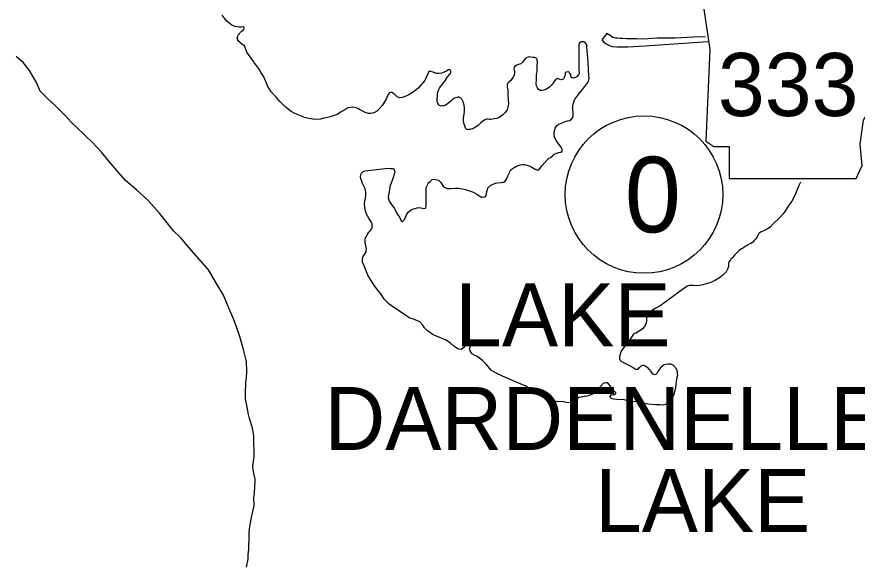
# Model space of a CAD drawing. Extents: x 31699 to 244310, y -8841 to 11474.
# Drawn here: x 95308.6 to 95778.2, y 4155.7 to 4462.2 of the extents above; entities that cross this region are included whole.
import ezdxf

# ---------------------------------------------------------------- set-up
doc = ezdxf.new("R2010")
doc.units = 0
for name, color, linetype in [('G-ANNO-TEXT', 7, 'Continuous'), ('R_Border Notes', 7, 'Continuous'), ('R_Draft', 7, 'Continuous'), ('R_Logo', 7, 'Continuous')]:
    doc.layers.add(name, color=color, linetype=linetype)

msp = doc.modelspace()

# ---------------------------------------------------------------- linework, layer by layer
at = {"layer": 'G-ANNO-TEXT'}
msp.add_lwpolyline([(95690.79, 4477.79), (95695.87, 4443.96), (95693.61, 4392.64), (95698.12, 4389.82), (95706.58, 4389.82), (95706.58, 4371.77), (95777.64, 4371.77), (95781.02, 4379.1), (95779.89, 4390.95), (95781.59, 4404.48), (95787.79, 4415.2), (95791.74, 4423.09), (95797.38, 4431.55), (95800.76, 4440.57), (95803.58, 4447.9), (95808.65, 4454.11), (95809.78, 4458.05), (95807.53, 4460.87), (95790.05, 4460.87), (95793.99, 4468.77), (95794.56, 4473.84), (95792.22, 4477.74)], close=True, dxfattribs=at)
at = {"layer": 'R_Border Notes'}
msp.add_circle((95659.04, 4362.88), 44, dxfattribs=at)
at = {"layer": 'R_Draft'}
for points in [[(95435.67, 4446.36), (95435.21, 4446.14), (95434.18, 4447.04), (95433.49, 4447.75), (95433.22, 4448.01), (95432.47, 4448.66), (95432.19, 4449.12), (95432.04, 4449.72), (95431.82, 4450.31), (95432, 4450.85), (95432.11, 4451.66), (95432.49, 4452.34), (95432.88, 4452.62), (95433.08, 4452.69), (95433.46, 4453.37), (95433.84, 4453.85), (95434.23, 4454.2), (95434.49, 4454.47), (95435.2, 4454.96), (95435.33, 4455.17), (95435.52, 4455.37), (95435.65, 4455.71), (95435.64, 4455.98), (95435.49, 4456.37), (95434.82, 4456.69), (95434.03, 4456.4), (95433.56, 4456.38), (95432.76, 4456.49), (95430.48, 4456.89), (95428.67, 4457.57), (95427.03, 4458.92), (95425.87, 4459.82), (95424.48, 4461.65), (95423.3, 4463.22)], [(95693.33, 4450.95), (95686.8, 4450.79), (95676.42, 4450.35), (95666.64, 4450.19), (95658.39, 4449.79), (95654.93, 4449.87), (95649.2, 4449.97), (95647.13, 4450.14), (95645.67, 4450.18), (95644.27, 4450.23), (95643.14, 4450.21), (95642.4, 4450.4), (95641.6, 4450.72), (95640.18, 4451.83), (95638.23, 4452.8), (95635.49, 4449.42)], [(95587.78, 4378.76), (95589.96, 4379.46), (95591.43, 4379.69), (95592.36, 4379.7), (95593.56, 4379.39), (95595.3, 4378.68), (95596.38, 4378.1), (95597.25, 4377.65), (95598.26, 4377.13), (95599.2, 4376.61), (95600.2, 4376.76), (95600.72, 4377.03), (95601.5, 4378.32), (95602.22, 4379.13), (95605.23, 4382.65), (95605.95, 4383.13), (95606.74, 4383.67), (95608.05, 4384.76), (95608.91, 4385.38), (95610.03, 4385.86), (95611.29, 4386.35), (95612.62, 4386.64), (95613.34, 4387.12), (95613.32, 4388.25), (95612.64, 4389.58), (95611.07, 4391.55), (95610.32, 4392.61), (95609.57, 4393.8), (95609.02, 4395.06), (95608.87, 4395.72), (95608.85, 4397.06), (95609.09, 4398.6), (95609.47, 4399.94), (95610.38, 4401.49), (95611.5, 4402.24), (95613.35, 4403), (95615.2, 4403.7), (95616.33, 4403.99), (95617.39, 4404.34), (95618.38, 4404.82), (95619.23, 4405.97), (95619.41, 4406.91), (95619.4, 4407.71), (95619.38, 4408.91), (95619.29, 4410.24), (95619.27, 4411.11), (95619.25, 4412.58), (95619.56, 4414.05), (95619.75, 4414.72), (95620.26, 4415.8), (95621.24, 4417.28), (95622.35, 4418.57), (95623.78, 4420.46), (95624.7, 4421.61), (95626.39, 4423.91), (95627.24, 4424.99), (95627.95, 4426.27), (95628.32, 4427.74), (95628.29, 4430.01), (95628.06, 4431.81), (95627.95, 4434.41), (95627.93, 4435.61), (95627.84, 4436.81), (95627.44, 4441.28), (95627.28, 4442.47), (95627.27, 4443.14), (95627.1, 4445.41), (95627.02, 4446.21), (95627.02, 4446.27), (95627.09, 4446.28), (95627.02, 4446.27), (95626.95, 4446.74), (95626.74, 4447.14), (95626.33, 4447.66), (95626.06, 4447.86), (95625.39, 4448.25), (95624.86, 4448.31), (95623.99, 4448.29), (95623.2, 4447.81), (95622.62, 4446.87), (95622.55, 4443.13), (95622.67, 4439.8), (95622.7, 4437.79), (95622.6, 4435.92), (95622.62, 4434.32), (95622.65, 4432.79), (95622.74, 4430.99), (95622.75, 4430.45), (95622.56, 4429.92), (95622.04, 4429.37), (95621.71, 4428.9), (95620.46, 4428.15), (95620.19, 4428.08), (95619.4, 4428), (95619.06, 4428.06), (95618.79, 4428.19), (95618.39, 4428.58), (95618.32, 4428.85), (95618.25, 4429.11), (95618.17, 4429.64), (95618.17, 4430.05)], [(95635.49, 4449.42), (95636.38, 4448.16), (95637.46, 4447.38), (95638.67, 4446.66), (95640.21, 4445.96), (95641.41, 4445.71), (95643.95, 4445.42), (95646.48, 4445.39), (95649.81, 4445.44), (95659.65, 4446.07), (95694.7, 4448.39)], [(95511.35, 4410.95), (95509.78, 4409.39), (95508.46, 4408.7), (95507.4, 4408.35), (95506.34, 4408.13), (95504.87, 4408.24), (95502.79, 4409.01), (95501.12, 4409.78), (95500.11, 4410.43), (95499.1, 4410.88), (95498.16, 4411.34), (95497.36, 4411.59), (95496.16, 4411.7), (95494.89, 4411.62), (95493.5, 4411.26), (95491.85, 4410.23), (95490.2, 4409.34), (95488.76, 4408.31), (95487.9, 4407.77), (95486.71, 4407.28), (95485.45, 4406.79), (95483.66, 4406.23), (95482.27, 4405.87), (95480.15, 4405.5), (95478.29, 4405.07), (95475.1, 4404.89), (95471.69, 4405.37), (95469.29, 4405.86), (95466.74, 4407.09), (95463.92, 4408.24), (95461.91, 4409.28), (95458.34, 4412.02), (95455.63, 4414.85), (95453.52, 4417.28), (95450.74, 4420.37), (95448.83, 4423.21), (95447.86, 4425.73), (95447.44, 4426.79), (95446.75, 4428.32), (95445.93, 4429.77), (95445.04, 4431.03), (95444.63, 4432.02), (95443.6, 4433.47), (95442.51, 4434.92), (95441.36, 4436.37), (95441.01, 4437.04), (95438.09, 4441.06), (95437.13, 4442.51), (95436.64, 4443.97), (95436.16, 4445.03), (95435.67, 4446.36)], [(95618.17, 4430.05), (95617.49, 4430.83), (95617.21, 4431.36), (95616.61, 4431.42), (95615.68, 4431.27), (95615.35, 4431.2), (95615.15, 4431.06), (95615.02, 4430.73), (95614.97, 4430.06), (95614.78, 4429.19), (95614.66, 4428.85), (95614.53, 4428.38), (95614.34, 4427.98), (95614.08, 4427.51), (95613.88, 4427.44), (95613.28, 4427.23), (95613.22, 4427.23), (95612.62, 4427.08), (95611.62, 4427.4), (95610.88, 4427.66), (95610.81, 4427.66), (95610.48, 4427.58), (95610.02, 4427.44), (95609.75, 4427.31), (95609.36, 4426.9), (95609.23, 4426.56), (95608.51, 4425.75), (95607.94, 4424.41), (95607.15, 4423.79), (95606.3, 4422.98), (95605.38, 4422.29), (95604.65, 4421.75), (95604.19, 4421.54), (95603.13, 4421.26), (95601.87, 4421.04), (95601, 4421.02), (95600.13, 4421.68), (95599.45, 4422.47), (95598.96, 4423.66), (95598.81, 4424.72), (95598.97, 4427.33), (95598.94, 4428.93), (95598.99, 4430), (95599.3, 4431.41), (95599.4, 4433.28), (95599.32, 4434.01), (95599.37, 4435.35), (95599.48, 4436.55), (95599.48, 4436.75), (95599.47, 4437.15), (95599.4, 4437.41), (95599.32, 4438.28), (95599.11, 4438.74), (95598.71, 4439.07), (95598.31, 4439.2), (95597.84, 4439.39), (95596.84, 4439.44), (95595.84, 4439.63), (95594.97, 4439.81), (95594.24, 4439.67), (95593.51, 4439.39), (95593.18, 4439.12), (95592.66, 4438.64), (95591.74, 4437.62), (95591.22, 4436.88), (95590.24, 4436), (95589.71, 4435.72), (95588.91, 4435.51), (95588.25, 4435.3), (95587.79, 4435.09), (95587.39, 4435.02), (95587.06, 4434.74), (95586.6, 4434.27), (95586.41, 4433.8), (95586.35, 4433.2), (95586.43, 4432.8), (95586.43, 4432.4), (95586.65, 4431.73), (95586.66, 4430.67), (95586.41, 4429.79), (95585.9, 4428.52), (95585.38, 4427.71), (95584.6, 4426.56), (95583.61, 4425.74), (95582.89, 4425.07), (95582.51, 4424.19), (95582.66, 4422.93), (95582.89, 4421.46), (95583, 4418.53), (95583.24, 4415.93), (95583.28, 4413.53), (95583.04, 4411.79), (95582.54, 4410.18), (95581.3, 4408.55), (95579.92, 4407.26), (95578.21, 4405.97), (95576.89, 4405.35), (95575.36, 4405.12), (95573.44, 4404.89), (95572.64, 4404.88), (95571.97, 4404.93)], [(95571.97, 4404.93), (95571.7, 4405.06), (95571.11, 4404.92), (95570.05, 4404.57), (95568.79, 4403.74), (95567.94, 4402.93), (95566.63, 4401.57), (95565.45, 4400.82), (95563.93, 4399.93), (95563.67, 4399.79), (95563.27, 4399.65), (95562.34, 4399.37), (95561.88, 4399.29), (95560.95, 4399.15), (95560.35, 4399.14), (95559.94, 4399.4), (95559.4, 4400.05), (95558.91, 4401.25), (95558.57, 4402.24), (95558.27, 4404.04), (95558.24, 4405.84), (95558.54, 4407.78), (95558.72, 4409.25), (95558.75, 4411.39), (95558.6, 4412.59), (95558.17, 4414.38), (95557.48, 4415.84), (95557.34, 4416.17), (95556.66, 4416.76), (95555.32, 4417.41), (95555.12, 4417.4), (95554.39, 4417.19), (95553.14, 4416.7), (95552.08, 4415.95), (95551.03, 4415.14), (95550.05, 4414.05), (95549.13, 4413.37), (95548.2, 4412.89), (95547.08, 4412.53), (95546.48, 4412.39), (95545.82, 4412.31), (95544.75, 4412.56), (95544.41, 4413.09), (95543.79, 4413.95), (95543.51, 4414.75), (95543.49, 4416.21), (95543.59, 4417.88), (95543.64, 4419.29), (95543.76, 4420.16), (95544.14, 4421.16), (95545.05, 4422.71), (95546.61, 4424.81), (95548.11, 4426.77), (95549.34, 4428.66), (95549.6, 4429.06), (95550.39, 4430.01), (95550.71, 4430.35), (95551.04, 4430.82), (95551.16, 4431.42), (95551.09, 4431.89), (95550.88, 4432.29), (95550.61, 4432.55), (95550.28, 4432.54), (95549.68, 4432.53), (95548.63, 4431.85), (95547.3, 4431.29), (95545.91, 4430.74), (95544.45, 4430.51), (95542.99, 4430.49), (95542.12, 4430.87), (95541.58, 4431.07), (95541.25, 4431.19), (95540.44, 4431.51), (95539.64, 4431.77), (95539.24, 4431.76), (95539.18, 4431.63), (95538.58, 4431.22), (95538.46, 4430.81), (95536.66, 4426.65), (95535.55, 4425.36), (95534.18, 4423.74), (95532.8, 4422.31), (95532.02, 4421.5), (95530.9, 4420.61), (95529.78, 4419.86), (95528.2, 4418.9), (95526.48, 4418.14), (95523.97, 4417.16), (95522.5, 4416.94), (95521.1, 4417.58), (95520.15, 4418.37), (95519.81, 4418.76), (95519.47, 4419.03), (95518.67, 4419.61), (95518.06, 4419.87), (95517.53, 4420), (95516.8, 4419.78), (95515.89, 4418.63), (95515.19, 4416.55), (95512.92, 4412.91), (95511.35, 4410.95)], [(95503.36, 4353.82), (95503.07, 4355.62), (95502.96, 4357.95), (95503.33, 4360.16), (95503.7, 4362.04), (95503.66, 4364.17), (95503.23, 4366.1), (95501.78, 4369.08), (95501.3, 4370.27), (95500.81, 4371.6), (95500.59, 4372.93), (95500.84, 4374), (95501.22, 4374.88), (95502.07, 4375.69), (95503.07, 4376.11), (95516.09, 4377.59), (95517.49, 4377.48), (95518.43, 4377.36), (95519.03, 4377.17), (95519.5, 4376.78), (95519.79, 4375.65), (95519.6, 4374.78), (95519.16, 4372.97), (95518.59, 4371.36), (95517.83, 4369.28), (95517.31, 4367.93), (95516.88, 4365.92), (95516.64, 4364.32), (95516.34, 4362.64), (95516.16, 4361.17), (95516.66, 4359.25), (95517.75, 4357.53), (95519.59, 4355.02), (95520.62, 4353.1), (95521.58, 4351.52), (95522.4, 4350.2), (95522.68, 4349.6), (95523.09, 4348.81), (95523.43, 4348.28), (95523.84, 4347.88), (95524.23, 4348.09), (95524.69, 4348.36), (95525.15, 4348.91), (95525.73, 4350.32), (95526.56, 4352), (95527.35, 4353.01), (95528.99, 4354.31), (95530.31, 4354.86), (95531.17, 4355.14), (95532.83, 4355.57), (95534.36, 4355.46), (95535.23, 4355.28), (95536.1, 4355.09), (95536.9, 4355.24), (95537.16, 4355.58), (95537.28, 4356.51), (95537.3, 4359.25), (95537.27, 4360.85), (95537.29, 4363.99), (95537.38, 4366.72), (95537.5, 4367.19), (95538.47, 4369.01), (95538.86, 4369.55), (95539.65, 4370.23), (95540.37, 4370.98), (95540.63, 4371.25), (95541.63, 4371.4), (95543.56, 4371.16), (95544.23, 4370.91), (95545.31, 4369.79), (95545.86, 4369.13), (95546.88, 4367.55), (95548.03, 4366.9), (95549.1, 4366.32), (95551.36, 4366.35), (95553.63, 4366.46), (95555.36, 4366.42), (95558.63, 4365.8), (95563.25, 4364.41), (95565.73, 4363.05), (95566.41, 4362.59), (95568.29, 4361.36), (95569.02, 4361.57), (95569.82, 4361.38), (95570.48, 4361.86), (95570.94, 4362.4), (95571.12, 4363.27), (95571.3, 4364.67), (95571.74, 4366.28), (95571.8, 4366.55), (95573.44, 4368.11), (95576.09, 4369.16), (95577.08, 4369.44), (95579.27, 4369.61), (95580.73, 4369.83), (95581.52, 4370.38), (95582.37, 4371.8), (95582.94, 4373.27), (95584.68, 4376.64), (95585.54, 4377.45), (95587.78, 4378.76)], [(95746.43, 4369.71), (95745.62, 4367.92), (95743.31, 4362.34), (95741.63, 4359.24), (95739.94, 4356.95), (95738.06, 4354.04), (95736.76, 4352.15), (95734.66, 4349.92), (95731.25, 4346.59), (95729.49, 4344.63), (95728.11, 4343.67), (95726.39, 4342.84), (95724.54, 4342.08), (95724.14, 4341.8), (95723.22, 4341.06), (95722.25, 4339.24), (95721.54, 4338.22), (95720.56, 4337.14), (95719.71, 4336.13), (95718.78, 4335.51), (95717.86, 4335.09), (95716.67, 4334.47), (95715.55, 4333.86), (95714.63, 4333.17), (95713.51, 4332.49), (95711.99, 4331.46), (95710.95, 4330.38), (95709.64, 4328.95), (95708.4, 4327.53), (95707.61, 4326.78), (95707.28, 4326.45), (95706.5, 4325.23), (95706.32, 4324.23), (95706.34, 4322.76), (95705.96, 4321.49), (95704.86, 4319.6), (95703.16, 4317.84), (95701.19, 4316.33), (95698.95, 4315.03), (95696.77, 4313.93), (95694.52, 4313.22), (95691.86, 4312.51), (95690.01, 4312.01), (95688.41, 4311.92)], [(95638.43, 4257.58), (95637.63, 4257.63), (95636.31, 4257.21), (95634.74, 4255.65), (95633.23, 4253.89), (95631.33, 4252.12), (95629.88, 4251.17), (95628.49, 4250.61), (95627.77, 4250.33), (95627.1, 4250.19), (95626.04, 4250.04), (95625.38, 4249.96), (95624.91, 4249.88), (95624.84, 4249.88), (95624.65, 4249.81), (95623.71, 4249.73), (95622.79, 4249.52), (95621.8, 4248.97), (95621.01, 4248.09), (95619.57, 4246.79), (95617.98, 4246.5), (95615.58, 4246.66), (95614.24, 4247.04), (95612.51, 4247.15), (95611.17, 4247.06), (95608.97, 4247.36), (95606.5, 4247.92), (95597.03, 4253.1), (95592.99, 4255.7), (95589.1, 4257.51), (95585.55, 4258.92), (95581.59, 4260.59), (95577.5, 4262.46), (95573.8, 4264.54), (95570.81, 4268.16), (95568.72, 4270.06), (95567.1, 4271.5), (95565.28, 4272.74), (95564.48, 4272.93), (95563.13, 4273.71), (95562.39, 4274.56), (95561.84, 4275.62), (95561.82, 4276.62), (95561.87, 4277.62), (95561.93, 4278.36), (95561.84, 4279.62), (95561.63, 4280.15), (95561.29, 4280.48), (95560.69, 4280.34), (95560.23, 4280), (95559.65, 4279.19), (95559.26, 4278.65), (95558.35, 4277.37), (95556.83, 4276.34), (95555.57, 4276.39), (95554.49, 4276.97), (95552.87, 4278.21), (95550.92, 4279.85), (95548.43, 4281.41), (95543.06, 4283.72), (95541.25, 4284.56), (95538.02, 4286.64), (95536.39, 4288.42), (95535.44, 4289.81), (95533.88, 4291.65), (95531.13, 4292.94), (95529.92, 4293.39), (95528.25, 4293.83), (95525.36, 4295.65), (95518.49, 4300.34), (95516.74, 4301.65), (95514.03, 4304.27), (95511.84, 4307.64), (95509.94, 4309.88), (95509.67, 4310.41), (95508.1, 4312.45), (95506.53, 4314.9), (95505.02, 4317.48), (95503.71, 4320.59), (95502.67, 4322.98), (95501.84, 4325.17), (95501.67, 4326.97), (95502.12, 4328.17), (95503.22, 4329.99), (95503.87, 4330.87), (95503.98, 4332.48), (95503.55, 4334.34), (95503.26, 4335.8), (95503.23, 4337.47), (95503.48, 4338.61), (95503.74, 4339.28), (95504.38, 4340.42), (95505.29, 4341.77), (95506.01, 4342.59), (95506.92, 4343.8), (95507.18, 4344.54), (95507.15, 4346.34), (95506.6, 4347.54), (95505.57, 4349.32), (95504.06, 4351.83), (95503.36, 4353.82)], [(95688.41, 4311.92), (95686.74, 4312.03), (95685.21, 4312.14), (95684.35, 4311.99), (95683.36, 4311.64), (95681.31, 4310.4), (95672.1, 4303.58), (95668.09, 4300.71), (95665.71, 4299.4), (95663.8, 4298.24), (95662.68, 4297.42), (95662.09, 4296.88), (95661.17, 4296.13), (95660.91, 4295.66), (95660.48, 4293.85), (95660.37, 4292.18), (95660.07, 4290.5), (95659.36, 4289.16), (95658.18, 4287.74), (95654.62, 4285.48), (95653.63, 4285.13), (95653.04, 4284.58), (95652.45, 4283.77), (95651.67, 4282.69), (95650.63, 4281.21), (95649.39, 4279.58), (95648.15, 4277.89), (95647.31, 4276.75), (95646.59, 4275.87), (95645.94, 4274.65), (95645.7, 4273.45), (95645.38, 4272.24), (95645.34, 4271.11), (95645.48, 4270.44), (95646.49, 4269.66), (95648.24, 4268.69), (95650.59, 4267.52), (95652.94, 4266.16), (95653.81, 4265.71), (95654.48, 4265.38), (95655.42, 4265.2), (95655.82, 4265.34), (95656.6, 4266.15), (95657.32, 4266.9), (95657.85, 4267.37), (95658.31, 4267.51), (95658.91, 4267.52), (95659.78, 4267.14), (95660.86, 4266.42), (95661.81, 4265.24), (95662.9, 4263.92), (95663.51, 4262.99), (95664.05, 4262.6), (95664.45, 4262.41), (95665.59, 4262.36), (95666.37, 4263.04), (95667.22, 4264.32), (95667.8, 4265.33), (95668.65, 4266.62), (95670.29, 4267.91), (95671.48, 4268.13), (95672.61, 4268.28), (95673.88, 4268.24), (95675.09, 4267.65), (95676.51, 4266.34), (95677.33, 4264.69), (95677.71, 4262.02), (95677.28, 4259.82), (95676.56, 4255.13), (95675.69, 4251.11), (95674.86, 4249.16), (95674.15, 4247.68), (95673.77, 4246.68), (95672.91, 4246.13), (95671.78, 4245.84), (95670, 4245.21), (95668.06, 4245.32), (95665.4, 4245.34), (95661.13, 4245.74), (95657.86, 4246.55), (95655.32, 4246.98), (95652.25, 4247.19), (95649.98, 4247.62), (95647.38, 4248.25), (95645.25, 4248.21), (95643.85, 4248.26), (95642.11, 4248.43), (95640.84, 4248.88), (95640.37, 4249.4), (95640.16, 4250), (95640.87, 4251.15), (95641.87, 4251.03), (95642.86, 4251.38), (95643.32, 4251.85), (95643.45, 4252.26), (95642.78, 4252.65), (95641.83, 4253.5), (95640.81, 4254.62), (95640.06, 4255.94), (95639.17, 4257.06), (95638.43, 4257.58)]]:
    msp.add_lwpolyline(points, dxfattribs=at)
at = {"layer": 'R_Logo'}
msp.add_lwpolyline([(95437.04, 4154.55), (95437.83, 4159.19), (95437.96, 4161.66), (95438.27, 4164.55), (95438.29, 4165.95), (95438.4, 4170.97), (95438.53, 4173.38), (95438.71, 4176.13), (95439.04, 4178.34), (95439.54, 4181.5), (95440.06, 4184.13), (95441.31, 4188.91), (95440.97, 4193.58), (95441.44, 4195.8), (95441.63, 4200.15), (95441.77, 4202.36), (95441.79, 4203.9), (95441.03, 4206.96), (95440.85, 4208.29), (95440.57, 4210.95), (95440.66, 4212.49), (95441.21, 4216.12), (95441.24, 4217.26), (95441.23, 4219.67), (95441.03, 4224.14), (95440.97, 4228.15), (95440.65, 4230.08), (95440.47, 4231.54), (95439.94, 4233.67), (95439.05, 4236.58), (95438.53, 4238.37), (95438.15, 4240.03), (95437.29, 4244.08), (95436.48, 4248.67), (95436.4, 4251.41), (95436.53, 4257.83), (95436.92, 4260.38), (95437.08, 4263.73), (95436.91, 4269.48), (95435.39, 4275.45), (95434.49, 4278.96), (95433.14, 4283.6), (95431.82, 4287.84), (95429.64, 4293.46), (95427.21, 4299.06), (95424.05, 4306.59), (95420.18, 4313.16), (95415.75, 4320.77), (95403.88, 4334.38), (95400.36, 4338.49), (95396.1, 4342.63), (95388.34, 4352.56), (95382, 4359.58), (95375.56, 4365.54), (95369.4, 4370.69), (95364.5, 4376.36), (95360.15, 4381.44), (95355.93, 4386.66), (95351.11, 4391.73), (95346.79, 4395.94), (95342.33, 4400.08), (95338.9, 4403.39), (95335.66, 4407.1), (95332.29, 4410.4), (95330.16, 4412.54), (95325.71, 4416.55), (95321.65, 4420.71), (95319.71, 4425.59), (95315.7, 4432.29), (95312.31, 4436.53), (95308.27, 4440.02)], dxfattribs=at)
msp.add_lwpolyline([(95437.04, 4154.55), (95437.83, 4159.19), (95437.96, 4161.66), (95438.27, 4164.55), (95438.29, 4165.95), (95438.4, 4170.97), (95438.53, 4173.38), (95438.71, 4176.13), (95439.04, 4178.34), (95439.54, 4181.5), (95440.06, 4184.13), (95441.31, 4188.91), (95440.97, 4193.58), (95441.44, 4195.8), (95441.63, 4200.15), (95441.77, 4202.36), (95441.79, 4203.9), (95441.03, 4206.96), (95440.85, 4208.29), (95440.57, 4210.95), (95440.66, 4212.49), (95441.21, 4216.12), (95441.24, 4217.26), (95441.23, 4219.67), (95441.03, 4224.14), (95440.97, 4228.15), (95440.65, 4230.08), (95440.47, 4231.54), (95439.94, 4233.67), (95439.05, 4236.58), (95438.53, 4238.37), (95438.15, 4240.03), (95437.29, 4244.08), (95436.48, 4248.67), (95436.4, 4251.41), (95436.53, 4257.83), (95436.92, 4260.38), (95437.08, 4263.73), (95436.91, 4269.48), (95435.39, 4275.45), (95434.49, 4278.96), (95433.14, 4283.6), (95431.82, 4287.84), (95429.64, 4293.46), (95427.21, 4299.06), (95424.05, 4306.59), (95420.18, 4313.16), (95415.75, 4320.77), (95403.88, 4334.38), (95400.36, 4338.49), (95396.1, 4342.63), (95388.34, 4352.56), (95382, 4359.58), (95375.56, 4365.54), (95369.4, 4370.69), (95364.5, 4376.36), (95360.15, 4381.44), (95355.93, 4386.66), (95351.11, 4391.73), (95346.79, 4395.94), (95342.33, 4400.08), (95338.9, 4403.39), (95335.66, 4407.1), (95332.29, 4410.4), (95330.16, 4412.54), (95325.71, 4416.55), (95321.65, 4420.71), (95319.71, 4425.59), (95315.7, 4432.29), (95312.31, 4436.53), (95308.27, 4440.02)], dxfattribs=at)

# ---------------------------------------------------------------- texts
at = {"layer": 'G-ANNO-TEXT'}
msp.add_text('333', height=35.2, dxfattribs=at).set_placement((95700.32, 4406.77))
at = {"layer": 'R_Border Notes'}
msp.add_text('0', height=42.24, dxfattribs=at).set_placement((95648.28, 4341.76))
at = {"layer": 'R_Draft'}
for s, p in [('LAKE', (95553.49, 4278.09)), ('DARDENELLE', (95480.49, 4220.11)), ('LAKE', (95631.63, 4174.28))]:
    msp.add_text(s, height=35.2, dxfattribs=at).set_placement(p)

doc.saveas('drawing.dxf')
